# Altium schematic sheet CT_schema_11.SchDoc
size 274 x 160 mm
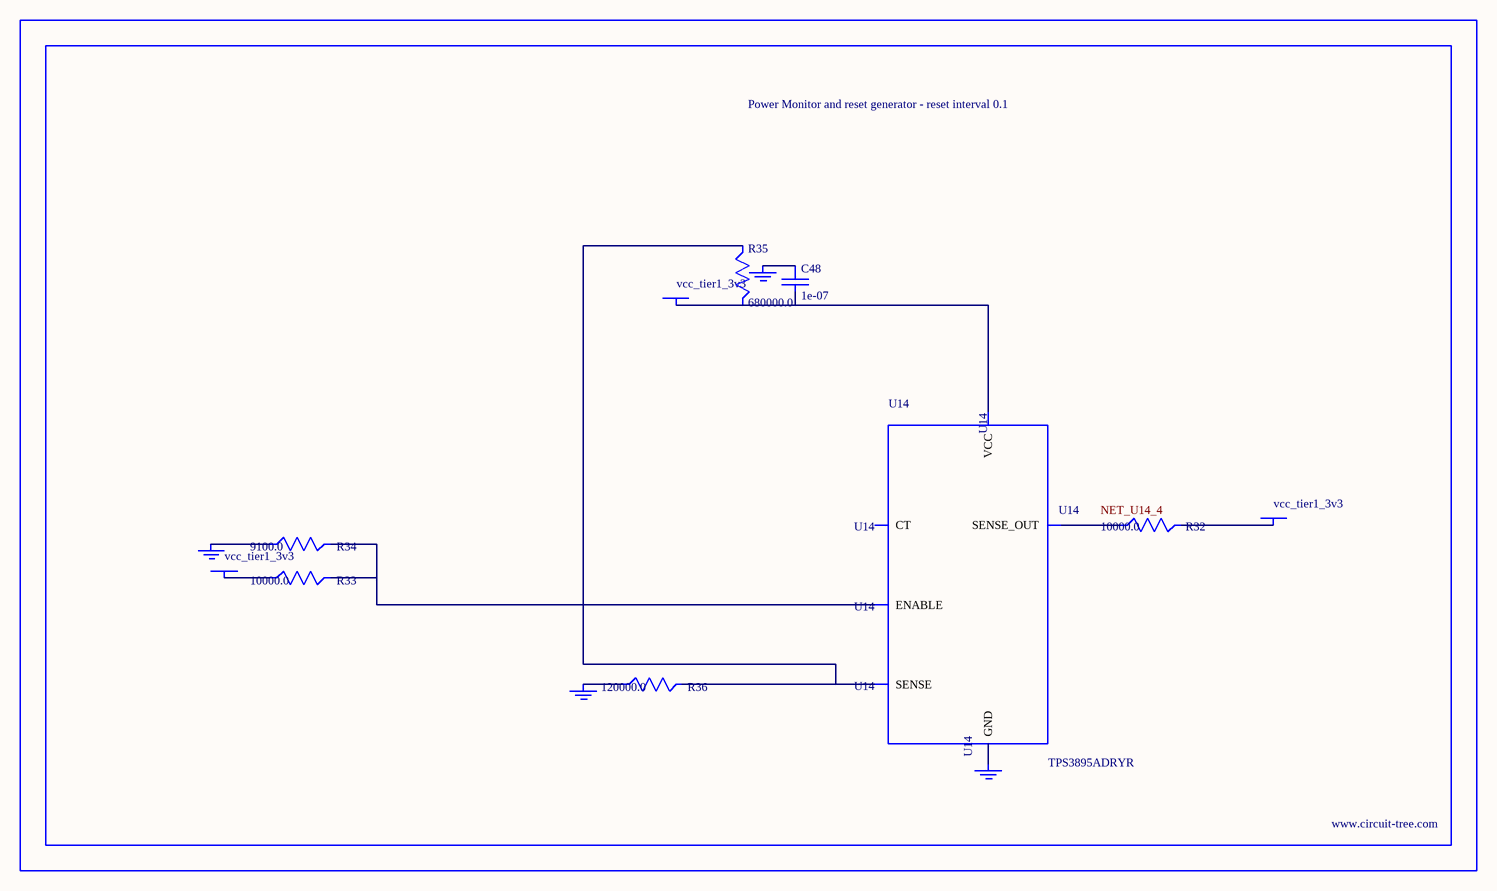
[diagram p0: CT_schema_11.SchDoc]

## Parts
BORDER10  (no value)
C48  1e-07  [C0402]
GND_INSTANCE_10_0  (no value)
GND_INSTANCE_10_1  (no value)
GND_INSTANCE_10_2  (no value)
GND_INSTANCE_10_3  (no value)
POWER_INSTANCE_10_0  vcc_tier1_3v3
POWER_INSTANCE_10_1  vcc_tier1_3v3
POWER_INSTANCE_10_2  vcc_tier1_3v3
R32  10000.0  [R0603]
R33  10000.0  [R0603]
R34  9100.0  [R0603]
R35  680000.0  [R0603]
R36  120000.0  [R0603]
U14  TPS3895ADRYR  [SON-6]

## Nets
NetC48_1: C48.1 GND_INSTANCE_10_2.0(GND)
NetC48_2: C48.2 POWER_INSTANCE_10_2.0(PWR) R35.2 U14.6(VCC)
NetGND_INSTANCE_10_0_0: GND_INSTANCE_10_0.0(GND) R34.1
NetGND_INSTANCE_10_1_0: GND_INSTANCE_10_1.0(GND) R36.1
NetGND_INSTANCE_10_3_0: GND_INSTANCE_10_3.0(GND) U14.2(GND)
NetPOWER_INSTANCE_10_0_0: POWER_INSTANCE_10_0.0(PWR) R33.1
NetPOWER_INSTANCE_10_1_0: POWER_INSTANCE_10_1.0(PWR) R32.2
NetR32_1: R32.1 U14.4(SENSE_OUT)
NetR33_2: R33.2 R34.2 U14.1(ENABLE)
NetR35_1: R35.1 R36.2 U14.3(SENSE)

Not connected (* = marked no-connect by the designer): U14 5(CT)

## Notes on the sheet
- Labels drawn without touching a wire or pin: NET_U14_4

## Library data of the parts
BORDER10 = BORDER_PAGE10
C48 = C0402C104K3RACTU
GND_INSTANCE_10_0-GND_INSTANCE_10_3 = GND
POWER_INSTANCE_10_0-POWER_INSTANCE_10_2 = PWR
R32 R33 = RC0603JR-0710KL
R34 = RC0603JR-079K1L
R35 = RC0603JR-07680KL
R36 = RC0603JR-07120KL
